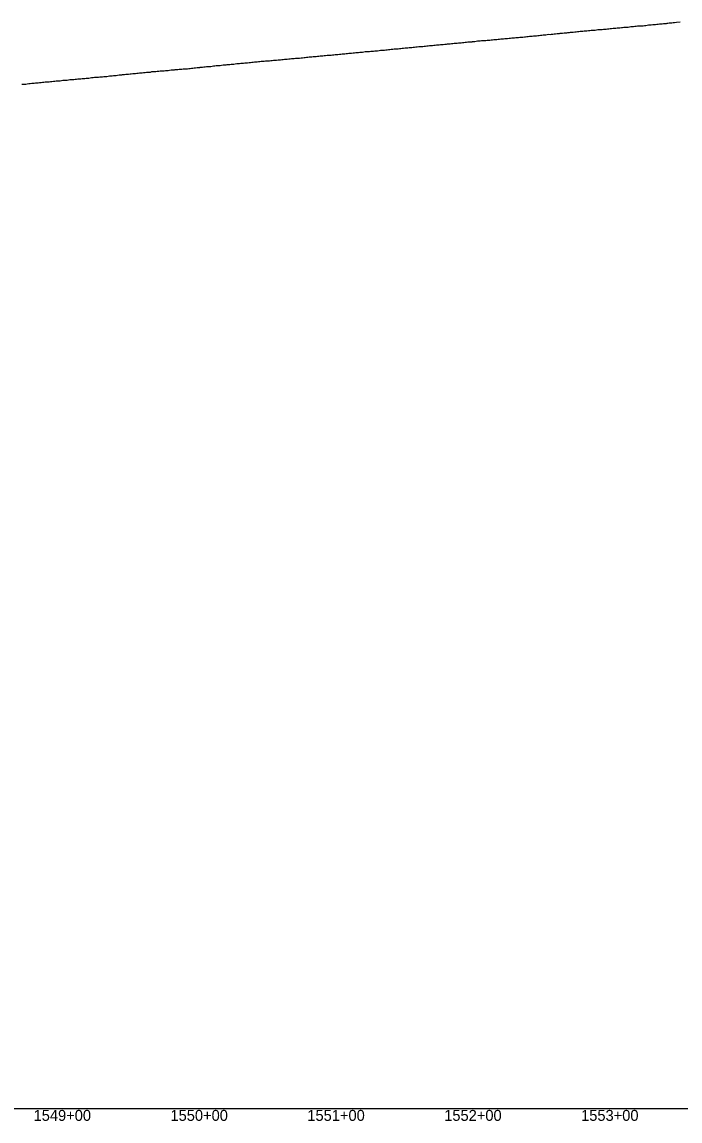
# Model space of a CAD drawing. Extents: x -3793 to 50787, y -1075 to 6138.
# Drawn here: x 42310 to 42791, y -1009 to -206 of the extents above; entities that cross this region are included whole.
import ezdxf

# ---------------------------------------------------------------- set-up
doc = ezdxf.new("R2010")
doc.units = 0
for name, color, linetype in [('RD_DDB_Profile_EX', 7, 'Continuous'), ('RD_DDB_StaTX', 7, 'Continuous'), ('RD_GPK_Profile_Cell', 7, 'Continuous')]:
    doc.layers.add(name, color=color, linetype=linetype)

msp = doc.modelspace()

# ---------------------------------------------------------------- linework, layer by layer
at = {"layer": 'RD_DDB_Profile_EX'}
for points in [[(42724.274181, -211.89876), (42724.927492, -211.898515), (42725.275265, -211.898255), (42726.276309, -211.698115), (42727.276259, -211.64869), (42728.277302, -211.59839), (42729.278346, -211.497995), (42730.278295, -211.298795), (42731.279323, -211.19861), (42732.279277, -211.098995), (42733.280318, -211.048705), (42734.399296, -210.980535), (42735.271305, -210.848945), (42736.272287, -210.79872), (42737.27327, -210.74842), (42738.273158, -210.649145), (42739.274141, -210.548915), (42740.275123, -210.44869), (42741.275004, -210.249375), (42742.275985, -210.199115), (42743.275878, -210.199765), (42743.8711, -210.140165), (42744.276835, -210.099565), (42745.277756, -209.999415), (42746.267781, -209.900105), (42746.949465, -209.83188), (42747.268545, -209.79995), (42748.5483, -209.72211), (42749.270087, -209.650545), (42750.270777, -209.50044), (42751.271468, -209.450235), (42752.272392, -209.40094), (42753.342904, -209.29735), (42754.274056, -209.251575), (42755.274784, -209.00171), (42756.275528, -208.951555), (42757.276496, -208.852635), (42758.267243, -208.7026), (42759.267986, -208.652215), (42760.268962, -208.50335), (42761.269704, -208.453125), (42762.270447, -208.35291), (42762.814708, -208.35338), (42763.271447, -208.353645), (42764.272242, -208.303475), (42765.273229, -208.154755), (42766.274024, -208.054335), (42767.27482, -207.95433), (42768.275839, -207.80544), (42769.276635, -207.755185), (42770.267463, -207.605635), (42771.26849, -207.506865), (42772.286512, -207.45485), (42773.270133, -207.356355), (42774.271213, -207.257665), (42775.271995, -207.15774), (42776.273065, -207.058), (42777.273914, -206.95845), (42778.274762, -206.907745), (42779.275832, -206.709495), (42780.276681, -206.65913), (42781.267601, -206.65917), (42781.758316, -206.561595), (42782.268708, -206.461585), (42783.269611, -206.261745), (42784.270743, -206.26128), (42785.271537, -206.21142), (42786.277389, -206.06155), (42787.266982, -205.914335), (42788.61336, -205.809825), (42791.23012, -205.599205)], [(42627.305699, -221.109085), (42628.306014, -221.00843), (42629.306328, -220.9078), (42630.306424, -220.807535), (42631.30678, -220.757025), (42632.297195, -220.65685), (42633.29755, -220.5567), (42634.297904, -220.45655), (42635.298028, -220.256135), (42636.298383, -220.20597), (42637.298738, -220.15554), (42638.299092, -220.055125), (42639.299216, -220.00394), (42639.681256, -219.927505), (42640.299557, -219.804445), (42641.299956, -219.754355), (42642.300355, -219.604265), (42643.300754, -219.504175), (42644.300929, -219.403175), (42645.291345, -219.35306), (42646.291743, -219.253105), (42647.292142, -219.20288), (42648.292308, -219.051965), (42649.292712, -219.05172), (42650.293154, -218.95187), (42651.293596, -218.851695), (42652.294039, -218.8016), (42653.294248, -218.70072), (42654.294691, -218.65071), (42655.295133, -218.500735), (42656.295568, -218.40076), (42657.295976, -218.299855), (42658.296437, -218.199845), (42658.624864, -218.166675), (42659.286884, -218.099855), (42660.287279, -217.99993), (42661.287673, -217.89999), (42662.289167, -217.84909), (42663.289561, -217.74916), (42664.289957, -217.69919), (42665.290351, -217.599295), (42666.29183, -217.54832), (42667.292225, -217.39846), (42668.292609, -217.29848), (42669.292938, -217.248635), (42670.293268, -217.14879), (42671.294687, -216.997935), (42672.295018, -216.94809), (42673.285393, -216.848135), (42674.285721, -216.698365), (42675.287147, -216.59751), (42676.287477, -216.597565), (42677.568472, -216.43393), (42678.28807, -216.398035), (42679.288334, -216.248205), (42680.28969, -216.147505), (42681.289955, -216.047745), (42682.29022, -215.99781), (42683.290485, -215.898075), (42684.291841, -215.847125), (42685.292106, -215.797295), (42686.29237, -215.647755), (42687.282666, -215.548085), (42688.282863, -215.398425), (42689.284161, -215.34771), (42690.284359, -215.248045), (42691.284557, -215.098455), (42692.284755, -214.99883), (42693.286036, -214.89826), (42694.286237, -214.748625), (42695.286438, -214.59896), (42696.51208, -214.63791), (42697.28679, -214.59946), (42698.288018, -214.448905), (42699.288156, -214.29933), (42700.278327, -214.249675), (42701.367514, -214.1), (42702.279695, -214.0995), (42703.279829, -213.899875), (42703.615673, -213.88321), (42704.280321, -213.850235), (42705.280996, -213.70062), (42706.487718, -213.58969), (42707.282481, -213.549625), (42708.447634, -213.425265), (42709.283717, -213.299605), (42710.407551, -213.23146), (42711.284957, -213.099605), (42712.276161, -213.09904), (42713.276234, -212.999515), (42714.277402, -212.899065), (42715.455688, -212.77211), (42716.27859, -212.64911), (42717.279694, -212.49884), (42718.2808, -212.39841), (42719.280811, -212.298965), (42720.281915, -212.24861), (42721.281917, -212.04918), (42722.283019, -212.04873), (42723.274171, -211.99826), (42724.274181, -211.89876)], [(42532.331343, -230.115625), (42533.331716, -229.967155), (42534.332091, -229.86714), (42535.491413, -229.825125), (42536.332649, -229.864455), (42537.333059, -229.71691), (42538.33325, -229.616895), (42539.333656, -229.46949), (42540.334061, -229.37224), (42541.334257, -229.269335), (42542.334662, -229.120115), (42543.335067, -229.02089), (42544.335263, -228.97089), (42544.963217, -228.87723), (42545.335681, -228.822775), (42546.335907, -228.772825), (42547.336347, -228.67371), (42548.336574, -228.526025), (42549.326793, -228.47295), (42550.32702, -228.373005), (42551.327025, -228.32011), (42552.327252, -228.270155), (42553.327048, -228.12148), (42554.435021, -227.92268), (42555.327318, -227.920815), (42556.327366, -227.86915), (42557.327624, -227.769255), (42558.327671, -227.668575), (42559.327719, -227.6179), (42560.327981, -227.41982), (42561.328024, -227.269925), (42562.328071, -227.21914), (42563.328334, -227.16844), (42563.906825, -227.110155), (42564.328396, -227.067725), (42565.328691, -227.017915), (42566.318924, -226.965655), (42567.319001, -226.865045), (42568.319302, -226.76599), (42569.319375, -226.665335), (42570.319676, -226.61405), (42571.319753, -226.464175), (42572.319829, -226.314915), (42573.378629, -226.258535), (42574.320239, -226.163185), (42575.320444, -226.11277), (42576.320564, -226.013535), (42577.320681, -225.912335), (42578.321017, -225.81259), (42579.321137, -225.71204), (42580.321474, -225.513525), (42581.32159, -225.41291), (42582.321709, -225.312305), (42582.850433, -225.286025), (42583.322065, -225.261475), (42584.312323, -225.16152), (42585.312699, -225.160725), (42586.312852, -225.011345), (42587.313004, -224.911355), (42588.313382, -224.811715), (42589.313532, -224.71168), (42590.313684, -224.610155), (42591.314063, -224.460495), (42592.322236, -224.45751), (42593.31463, -224.211385), (42594.314822, -224.16043), (42595.315013, -224.159065), (42596.315337, -224.058985), (42597.31553, -224.00813), (42598.315945, -223.8599), (42599.31614, -223.759465), (42600.316335, -223.559885), (42601.306829, -223.50941), (42601.79404, -223.509195), (42602.307041, -223.50858), (42603.3075, -223.459045), (42604.307731, -223.358695), (42605.307877, -223.208755), (42606.308332, -223.109245), (42607.308567, -222.958875), (42608.309022, -222.90892), (42609.309254, -222.85856), (42610.309489, -222.70862), (42611.309946, -222.60955), (42612.310221, -222.55882), (42613.310714, -222.40982), (42614.310989, -222.30908), (42615.311264, -222.2092), (42616.30184, -222.109325), (42617.30211, -222.05902), (42618.302382, -222.00831), (42619.302883, -221.809285), (42620.303155, -221.75899), (42620.737648, -221.71581), (42621.303678, -221.660045), (42622.303992, -221.55892), (42623.304307, -221.50827), (42624.30485, -221.408845), (42625.305071, -221.35864), (42626.305385, -221.209315), (42627.305699, -221.109085)], [(42436.357744, -239.195235), (42437.347623, -239.146275), (42438.347667, -238.99632), (42439.34771, -238.846575), (42440.347754, -238.7964), (42440.773373, -238.75386), (42441.347792, -238.69627), (42442.347826, -238.54638), (42443.347861, -238.49649), (42444.347895, -238.34698), (42445.347929, -238.246895), (42446.347964, -238.197), (42447.347998, -238.09659), (42448.348032, -238.04688), (42449.348067, -237.797625), (42450.3481, -237.697725), (42451.348126, -237.64773), (42452.348151, -237.497755), (42453.348177, -237.448045), (42454.348203, -237.44798), (42455.348208, -237.298155), (42456.348235, -237.198335), (42457.348263, -237.048675), (42458.348291, -237.048615), (42459.348318, -236.898865), (42459.716981, -236.862065), (42460.348341, -236.799135), (42461.348362, -236.749325), (42461.99686, -236.652705), (42462.348371, -236.60042), (42463.348525, -236.50067), (42464.348679, -236.50089), (42465.348833, -236.35126), (42466.348987, -236.251675), (42467.349141, -236.05223), (42468.349071, -236.00124), (42469.339239, -235.901595), (42470.339427, -235.80182), (42471.339382, -235.75115), (42472.339569, -235.65147), (42473.339757, -235.551795), (42474.339712, -235.551165), (42475.339899, -235.351695), (42476.340087, -235.301935), (42477.340043, -235.151505), (42478.340229, -235.002105), (42478.660589, -234.986215), (42479.340437, -234.952335), (42480.340425, -234.85186), (42481.340643, -234.85198), (42482.340631, -234.701815), (42483.340849, -234.55204), (42484.341067, -234.45255), (42485.341035, -234.352195), (42486.341249, -234.30263), (42487.341463, -234.203055), (42488.341462, -234.102595), (42489.341707, -234.00296), (42490.341952, -233.953115), (42491.341976, -233.90277), (42492.342221, -233.80354), (42493.342245, -233.70286), (42494.34249, -233.55364), (42495.342735, -233.40412), (42496.342758, -233.40374), (42497.604197, -233.27844), (42498.343272, -233.20611), (42499.343328, -233.156135), (42500.343605, -233.05452), (42501.343881, -232.95502), (42502.333982, -232.85448), (42503.334264, -232.755505), (42504.334545, -232.706025), (42505.334598, -232.60573), (42506.334879, -232.55594), (42507.334942, -232.406285), (42508.335256, -232.3069), (42509.33557, -232.25716), (42510.335589, -232.15729), (42511.335897, -232.15753), (42512.336205, -232.058525), (42513.336293, -232.0075), (42514.336603, -231.90849), (42515.33691, -231.709985), (42516.547805, -231.559875), (42517.337334, -231.559975), (42518.337457, -231.40888), (42519.337797, -231.2605), (42520.338139, -231.161725), (42521.338262, -231.160505), (42522.338602, -231.06004), (42523.329054, -230.911205), (42524.329177, -230.812815), (42525.329523, -230.71476), (42526.32988, -230.71297), (42527.330038, -230.612895), (42528.330418, -230.36497), (42529.330798, -230.41576), (42530.330814, -230.31639), (42531.331187, -230.166465), (42532.331343, -230.115625)], [(42344.376435, -247.891735), (42345.37639, -247.742765), (42346.055334, -247.67498), (42346.376342, -247.64294), (42347.376281, -247.542765), (42348.376439, -247.54048), (42349.376377, -247.44119), (42350.376235, -247.291875), (42351.376176, -247.242135), (42352.376117, -247.14202), (42353.376059, -247.042665), (42354.376209, -247.04166), (42355.527138, -246.88481), (42356.376079, -246.84228), (42357.376007, -246.742975), (42358.375934, -246.643315), (42359.37586, -246.593015), (42360.375996, -246.443115), (42361.375922, -246.29378), (42362.375849, -246.1941), (42363.375776, -246.045005), (42364.375702, -245.94557), (42364.998942, -245.94574), (42365.375624, -245.945605), (42366.375745, -245.89465), (42367.375658, -245.745035), (42368.375571, -245.694705), (42369.375483, -245.595155), (42370.375397, -245.4958), (42371.37531, -245.39641), (42372.375432, -245.345745), (42373.375345, -245.19635), (42374.470746, -245.092025), (42375.375159, -245.047235), (42376.375058, -244.997605), (42377.374958, -244.84811), (42378.375067, -244.84737), (42379.374967, -244.64812), (42380.374866, -244.448775), (42381.364773, -244.29933), (42382.364667, -244.249755), (42382.891388, -244.19732), (42383.364678, -244.150235), (42383.942549, -244.09221), (42384.602306, -244.026235), (42385.364767, -243.95048), (42386.364704, -243.850115), (42386.696845, -243.816785), (42387.364747, -243.749805), (42387.746876, -243.711785), (42388.364807, -243.65034), (42389.444379, -243.588055), (42390.364828, -243.449735), (42391.364925, -243.349445), (42392.365022, -243.299065), (42393.414353, -243.193805), (42394.365205, -243.098495), (42395.36529, -242.94842), (42396.365375, -242.8482), (42397.36546, -242.847865), (42398.365545, -242.797385), (42399.36563, -242.64726), (42400.365715, -242.547165), (42401.3658, -242.397255), (42402.365885, -242.297045), (42402.886157, -242.270925), (42403.365964, -242.246315), (42404.366038, -242.245755), (42405.366112, -241.896975), (42406.366186, -241.896425), (42407.366258, -241.89563), (42408.356379, -241.79522), (42409.356454, -241.64551), (42410.35653, -241.595595), (42411.356605, -241.3462), (42412.357961, -241.29629), (42413.356525, -241.295985), (42414.356589, -241.24567), (42415.356653, -241.14511), (42416.356717, -241.095005), (42417.356782, -240.9949), (42418.356846, -240.795295), (42419.35691, -240.69545), (42420.356974, -240.645365), (42421.356985, -240.64501), (42421.829765, -240.550415), (42422.357043, -240.445485), (42423.357097, -240.3952), (42424.357151, -240.24571), (42425.357204, -240.095955), (42426.357257, -240.04567), (42427.357311, -240.045375), (42428.357364, -239.94508), (42429.357417, -239.84506), (42430.35747, -239.795035), (42431.357523, -239.794185), (42432.357567, -239.694785), (42433.357611, -239.594835), (42434.357655, -239.39488), (42435.3577, -239.29492), (42436.357744, -239.195235)], [(42310.385713, -251.044135), (42311.385721, -250.944105), (42312.385936, -250.942545), (42313.385943, -250.942155), (42314.385952, -250.79283), (42315.385959, -250.6928), (42316.385967, -250.493135), (42317.639922, -250.430185), (42318.386178, -250.39149), (42319.386169, -250.29193), (42320.386159, -250.142375), (42321.386149, -250.141615), (42322.386141, -249.99205), (42323.386131, -249.842885), (42324.386328, -249.741705), (42325.38632, -249.64174), (42326.38631, -249.542215), (42327.386297, -249.44269), (42328.38627, -249.34279), (42329.386243, -249.291635), (42330.386426, -249.240875), (42331.386399, -249.190995), (42332.386372, -249.09111), (42333.386347, -248.941655), (42334.38632, -248.841335), (42335.386295, -248.74144), (42336.58353, -248.601595), (42337.376528, -248.640405), (42338.376485, -248.59015), (42339.37644, -248.39036), (42340.376397, -248.241415), (42341.376352, -248.241185), (42342.376524, -248.09138), (42343.376481, -248.04111), (42344.376435, -247.891735)]]:
    msp.add_lwpolyline(points, dxfattribs=at)
at = {"layer": 'RD_GPK_Profile_Cell'}
msp.add_line((1000, -1000), (46610.921919, -1000), dxfattribs=at)

# ---------------------------------------------------------------- texts
at = {"layer": 'RD_DDB_StaTX'}
for s, p in [('1549+00', (42318.971301, -1009)), ('1550+00', (42418.971301, -1009)), ('1551+00', (42518.971301, -1009)), ('1552+00', (42618.971301, -1009)), ('1553+00', (42718.971301, -1009))]:
    msp.add_text(s, height=8, dxfattribs=at).set_placement(p)

doc.saveas('drawing.dxf')
